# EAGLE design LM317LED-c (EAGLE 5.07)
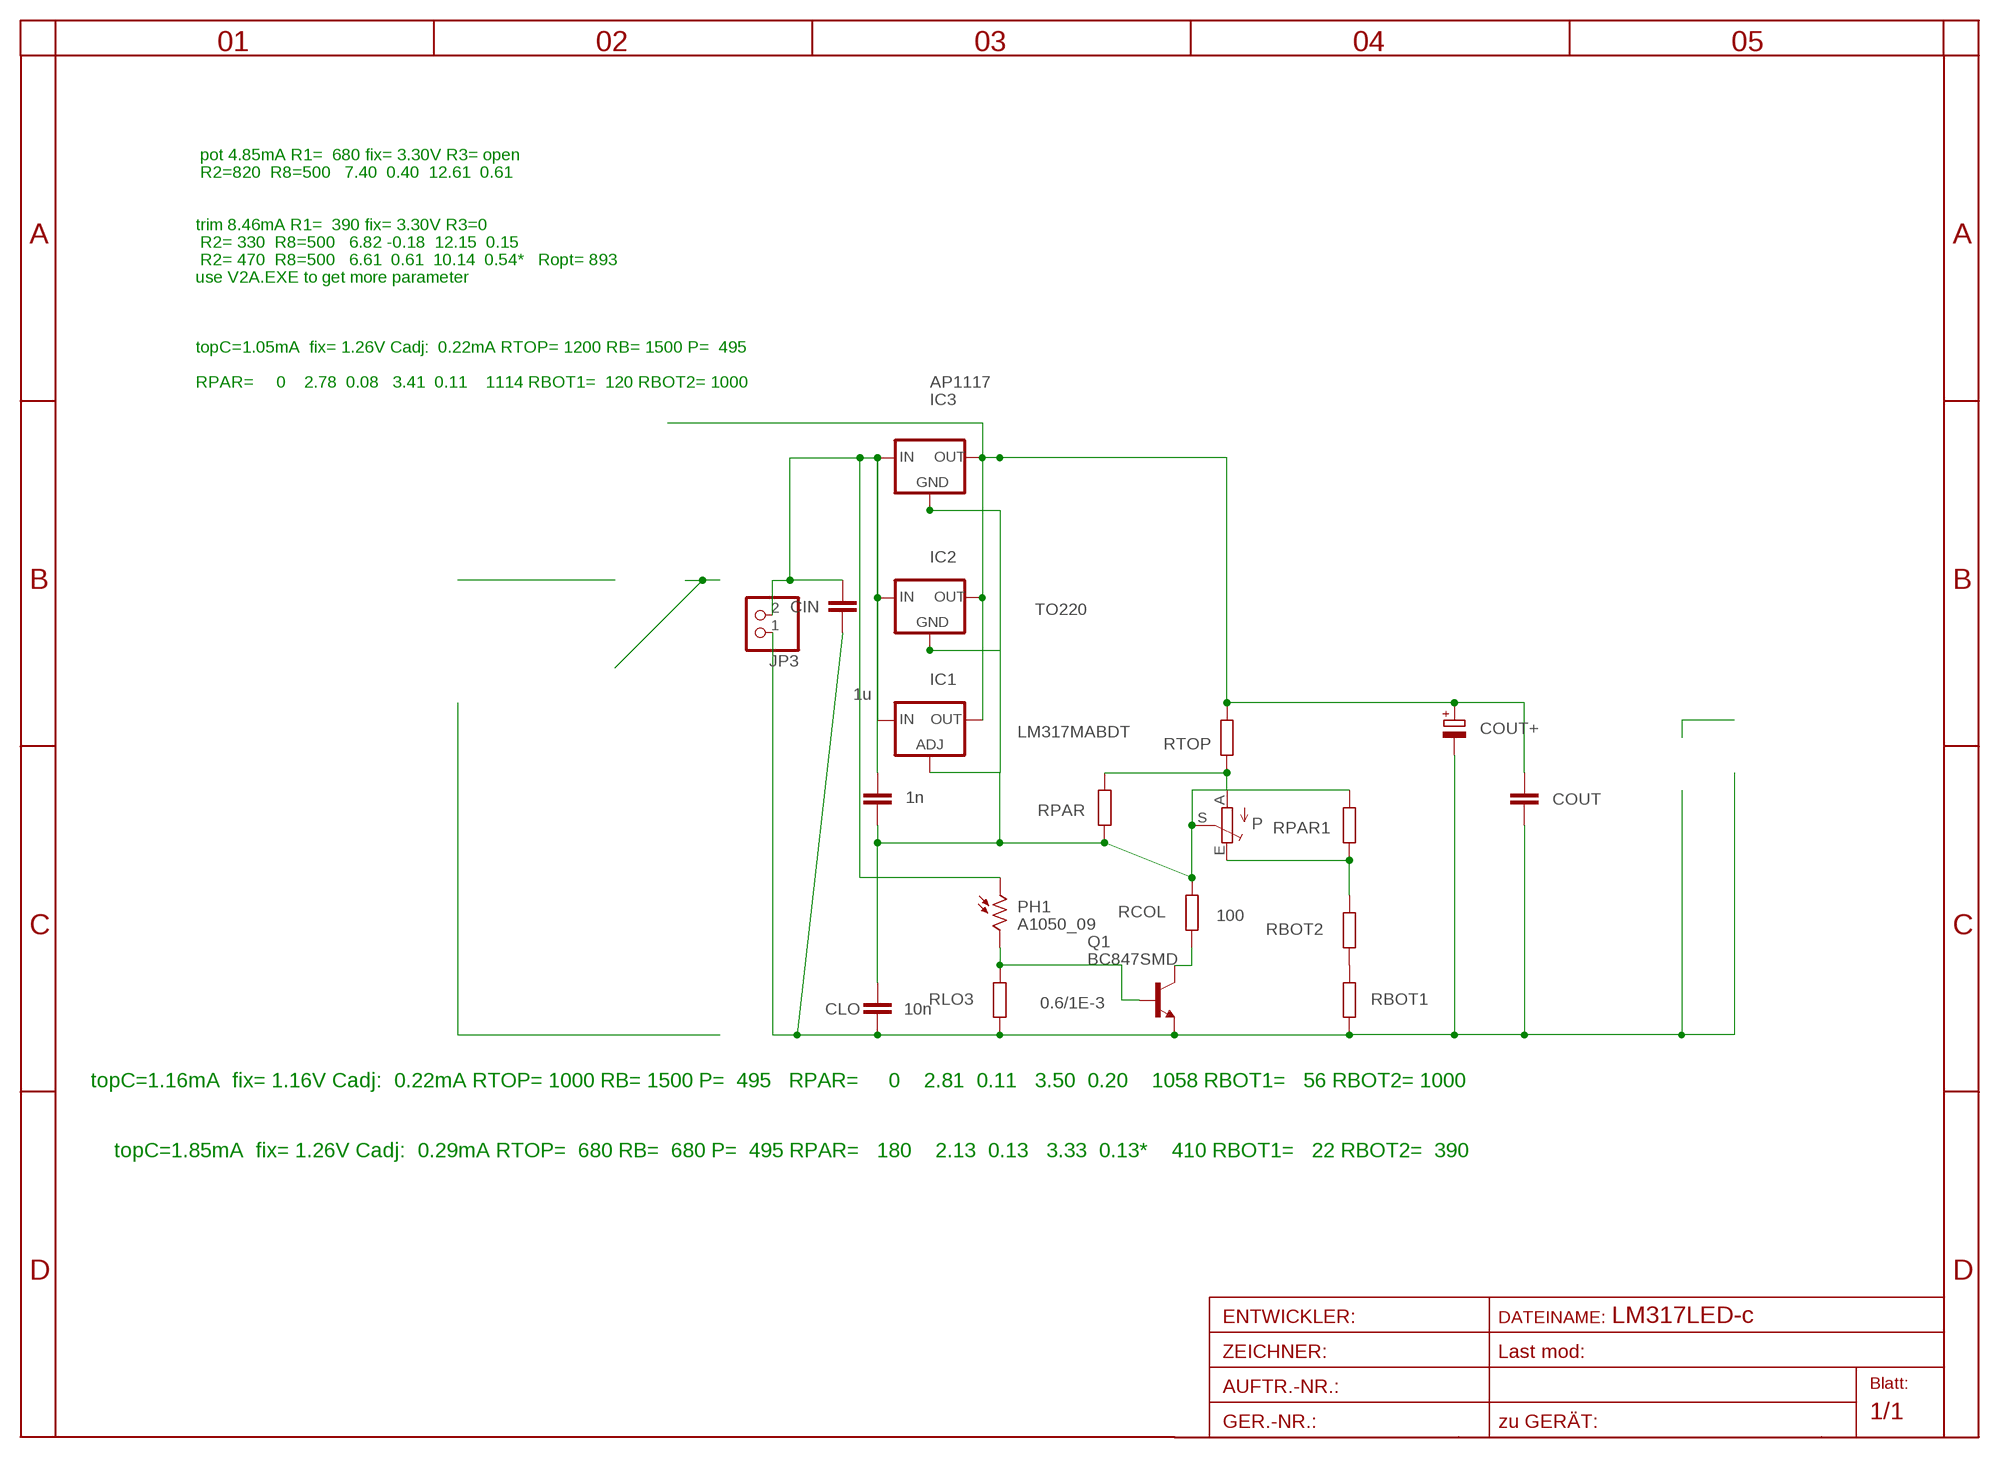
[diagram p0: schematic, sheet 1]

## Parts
CHI  1n  C-EUC0805  [C0805]
CIN  1u  C-EUC1206  [C1206]
CLO  10n  C-EUC0805  [C0805]
COUT  C-EUC1206  [C1206]
COUT+  CPOL-EUE7.5-16  [E7,5-16]
IC1  LM317MABDT  [DPACK]
IC2  TO220  78XXS  [78XXS]
IC3  AP1117  [SOT223]
JP3  PINHD-1X2STR  [1X02]
P  TRIM_EU-RAND160  [RANDL]
PH1  A1050_09  [T0-46-A10XX]
Q1  BC847SMD  [SOT23]
RBOT1  R-EU_R0805  [R0805]
RBOT2  R-EU_R0805  [R0805]
RCOL  100  R-EU_R0805  [R0805]
RLO3  0.6/1E-3  R-EU_R0805  [R0805]
RPAR  R-EU_R0805  [R0805]
RPAR1  R-EU_R0805  [R0805]
RTOP  R-EU_R0805  [R0805]

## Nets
GND: CIN.2 CLO.2 COUT+.- COUT.2 JP3.1 Q1.2(E) RBOT1.1 RLO3.1
IN: CHI.1 CIN.1 IC1.3(IN) IC2.IN IC3.3(IN) JP3.2 PH1.1
N$1: P.E RBOT2.2 RPAR1.1
N$2: RBOT1.2 RBOT2.1
N$3: Q1.3(C) RCOL.1
N$4: CHI.2 CLO.1 IC1.1(ADJ) IC2.GND IC3.1(GND) P.S RCOL.2 RPAR1.2 RPAR.1
N$5: PH1.2 Q1.1(B) RLO3.2
N$7: P.A RPAR.2 RTOP.1
OUT: COUT+.+ COUT.1 IC1.4(OUT) IC2.OUT IC3.2(OUT) IC3.4(TAB) RTOP.2

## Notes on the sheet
- pot 4.85mA R1=  680 fix= 3.30V R3= open
- R2=820  R8=500   7.40  0.40  12.61  0.61
- trim 8.46mA R1=  390 fix= 3.30V R3=0
- R2= 330  R8=500   6.82 -0.18  12.15  0.15
- R2= 470  R8=500   6.61  0.61  10.14  0.54*   Ropt= 893
- use V2A.EXE to get more parameter
- topC=1.05mA  fix= 1.26V Cadj:  0.22mA RTOP= 1200 RB= 1500 P=  495
- RPAR=     0    2.78  0.08   3.41  0.11    1114 RBOT1=  120 RBOT2= 1000
- topC=1.16mA  fix= 1.16V Cadj:  0.22mA RTOP= 1000 RB= 1500 P=  495   RPAR=     0    2.81  0.11   3.50  0.20    1058 RBOT1=   56 RBOT2= 1000
- topC=1.85mA  fix= 1.26V Cadj:  0.29mA RTOP=  680 RB=  680 P=  495 RPAR=   180    2.13  0.13   3.33  0.13*    410 RBOT1=   22 RBOT2=  390

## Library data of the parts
CHI CIN CLO COUT = rcl:C-EU: CAPACITOR, European symbol
COUT+ = rcl:CPOL-EU: POLARIZED CAPACITOR, European symbol
IC1 = v-reg:LM317?*: 500 mA Adjustable Output Positive Voltage Regulator Source: http://www.onsemi.co.jp .. LM317M-D.PDF
IC2 = v-reg:78XXS: VOLTAGE REGULATOR
IC3 = v-reg:AP1117
JP3 = pinhead:PINHD-1X2: PIN HEADER
P = pot:TRIM_EU-: POTENTIOMETER
PH1 = photo-elements:A10: Sensor Robust Light Sensing Applications
Q1 = transistor-npn:BC847*: NPN Transistor
RBOT1 RBOT2 RCOL RLO3 RPAR RPAR1 RTOP = rcl:R-EU_: RESISTOR, European symbol

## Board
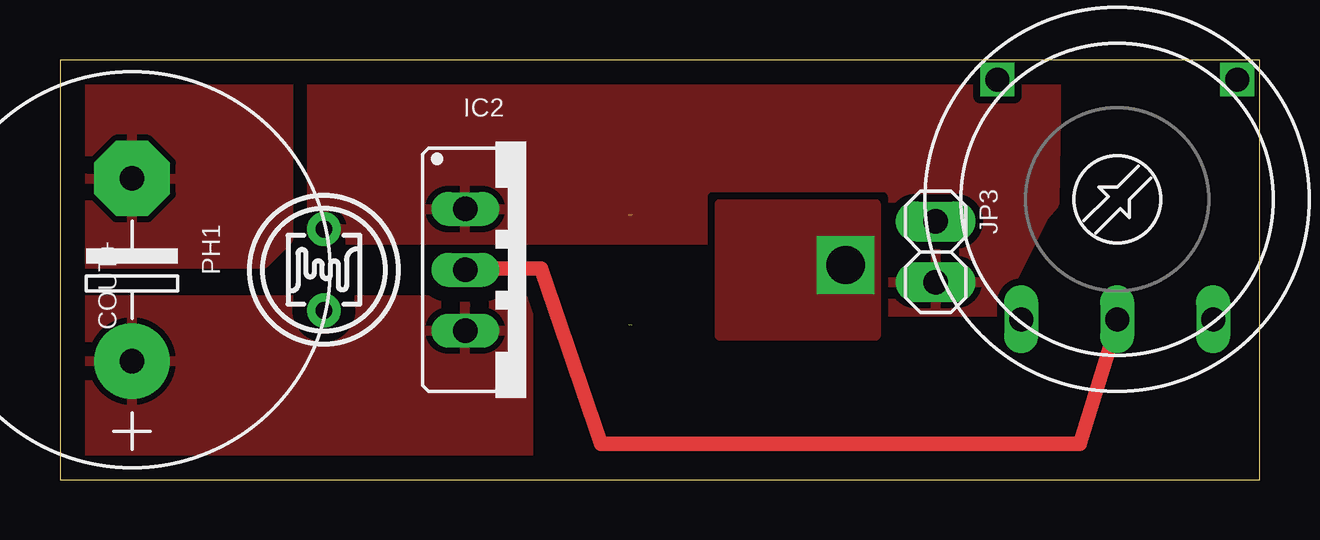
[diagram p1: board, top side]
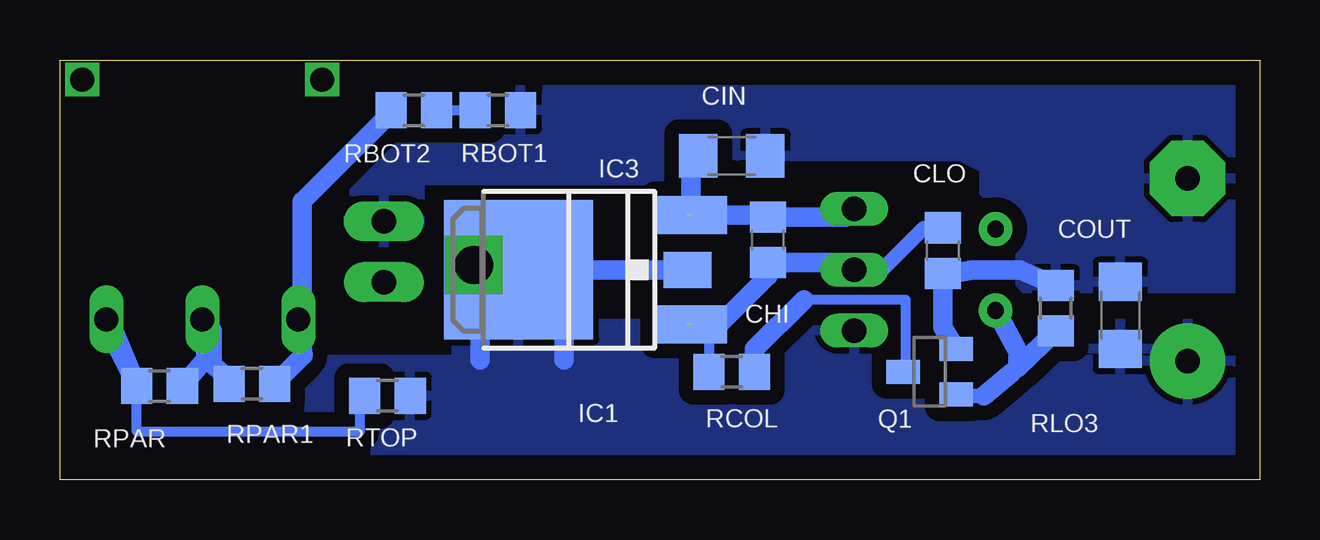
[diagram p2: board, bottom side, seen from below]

Size 50 x 17.5 mm. Coordinates in mm from the lower left corner, seen from the top.
Outline: 0,0 50,0 50,17.5 0,17.5 0,0
Copper layers (1*16): Top 0.035mm / dielectric 1.5mm / Bottom 0.035mm
Design rules "default *": minimum track width 10mil, minimum drill 20mil, track to track 8mil, track to pad 8mil, pad to pad 8mil, via to via 8mil, smd to smd 8mil, copper to edge 40mil, drill to drill 8mil, minimum pad ring 8mil, minimum via ring 8mil, stop-mask expansion 8mil, vias tented up to drill 0mil, thermal gap 10mil

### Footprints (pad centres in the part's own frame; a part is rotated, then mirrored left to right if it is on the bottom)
C0805 = smd 1.3 x 1.5: 1 -0.95,0; 2 0.95,0
C1206 = smd 1.6 x 1.8: 1 -1.4,0; 2 1.4,0
E7,5-16 = drill 1.016 pad 3.15 round: + -3.81,0 | drill 1.016 pad 3.15 octagon: - 3.81,0
DPACK = smd 1.6 x 3: 1 -2.28,-4.8; 3 2.28,-4.8 | smd 5.8 x 6.2: 4 0,2.38
78XXS = drill 1.016 long: GND 0,-2.54; IN -2.54,-2.54; OUT 2.54,-2.54
SOT223 = smd 1.5 x 2: 1 -2.3,-3.15; 2 0,-3.15; 3 2.3,-3.15 | smd 3.8 x 2: 4 0,3.15
1X02 = drill 1.016 pad 1.676 long: 1 -1.27,0; 2 1.27,0
RANDL = drill 1 long: A -4,5; E 4,5; S 0,5 | drill 1 square: P$1 -5,-5; P$2 5,-5
T0-46-A10XX = drill 0.7 pad 1.4 round: 1 -1.7,0; 2 1.7,0
SOT23 = smd 1 x 1.4: 1 -0.95,-1.1; 2 0.95,-1.1; 3 0,1.1
R0805 = smd 1.3 x 1.5: 1 -0.95,0; 2 0.95,0

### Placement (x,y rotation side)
CHI  20.5,10 270 bottom
CIN  22,13.5 0 bottom
CLO  13.2,9.55 270 bottom
COUT  5.8,6.85 90 bottom
COUT+  3,8.75 90 top
IC1  28.5,8.75 90 bottom
IC2  19.43,8.75 270 top
IC3  27,8.75 90 bottom
JP3  36.5,9.5 270 top
P  44.07,11.68 180 top
PH1  11,8.75 270 top
Q1  13.75,4.5 90 bottom
RBOT1  31.75,15.4 180 bottom
RBOT2  35.25,15.4 180 bottom
RCOL  22,4.5 180 bottom
RLO3  8.5,7.15 270 bottom
RPAR  45.85,3.9 180 bottom
RPAR1  42,4 180 bottom
RTOP  36.35,3.5 0 bottom

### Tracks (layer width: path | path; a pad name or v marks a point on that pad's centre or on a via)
GND
  Bottom 0.813: RLO3.1 10,8.75 12,8.75 13.3,8.5 CLO.2 13.2,6.35 Q1.2
  pour Bottom (isolate 0.61): 0,15.5 0.5,17.5 38,17 38,9.5 35,9.5 35,12.5 24.5,12.5 21.6,13.55 20.5,13.5 12.5,13.5 11.5,13 11.5,12 10,10.5 10,8 0,8
  pour Top (isolate 0.406, rank 3): 0,13.5 1,13.5 1,16.5 9.5,16.5 9.5,10 8.5,9 0,9
IN  (1 unrouted)
  Bottom 0.813: CIN.1 23.7,13.5 IC1.3 20.5,11.03 CHI.1 17.23,10.95 IC2.IN
  pour Top (isolate 0.305, rank 2): 41.5,16.57 41.5,15.5 41.44,11.5 41,11 39,7 34.5,7 34.5,10 10.5,10 10.5,16.5
N$1
  Bottom 0.813: RBOT2.2 36.2,15.3 39.9,11.6 39.9,6.46 P.E 39.87,5.18 RPAR1.1
N$2
  Bottom 0.406: RBOT2.1 RBOT1.2
N$3
  Bottom 0.406: 19,7.5 14.75,7.5 14.75,4.9 Q1.3
  Bottom 0.813: RCOL.1 21.05,5.45 19,7.5
N$4  (1 unrouted)
  Top 0.406: IC2.GND 17.24,8.8
  Top 0.61: P.S 43.87,5.87 42.5,1.5 22.55,1.5 20.05,8.8 17.24,8.8
  Bottom 0.406: RCOL.2 22.95,5.72 IC1.1 | 15.75,8.75 IC2.GND | CLO.1 14,10.5
  Bottom 0.61: 14,10.5 15.75,8.75
  Bottom 0.813: RPAR.1 43.9,5.05 P.S 43.65,6.21 43.65,4.8 42.95,4.2 RPAR1.2 | IC2.GND 17.19,9.05 CHI.2 20.5,8.5 22.5,6.5 23.67,6.5 IC1.1
N$5
  Bottom 0.406: 10.1,4.66 10.35,4.45 | 12.6,3.5 Q1.1
  Bottom 0.61: 11.5,3.5 12.6,3.5
  Bottom 0.813: RLO3.2 10.1,4.66 10.05,5.31 PH1.2 | 10.35,4.45 11.5,3.5
N$7
  Bottom 0.406: RTOP.1 37.5,3.5 37.5,2 46.8,2 RPAR.2
  Bottom 0.813: P.A 47.84,6.4 RPAR.2 47.7,5.72
OUT  (via drill 1.6)
  Bottom 0.813: IC3.2 IC3.4 | 29,5 29,6.5 | 32.5,5 32.5,6.5
  other vias: 32.75,8.95
  pour Bottom (isolate 0.61, rank 2): 27.5,11.5 33.5,11.5 33.5,5 44.5,5 44.5,0.5 0.5,0.5 0.5,6.5 27.5,6.5
  pour Top (isolate 0.61): 19,0 0,0 0.5,1.5 0.5,7.5 19.5,7.5 19.5,1
  pour Top (isolate 0.406): 27.5,11.5 34,11.5 34,6 27.5,6

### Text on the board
tStop: MICHAEL5.net
bStop: MICHAEL5.net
